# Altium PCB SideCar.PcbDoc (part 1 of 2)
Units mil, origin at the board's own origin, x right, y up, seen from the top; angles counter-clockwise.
Board outline 4800 x 2800 mil, 4 copper layers (Top Layer, GND Plane, Power Routing, Bottom Layer), stack 61.4 mil thick; 116 components, 136 nets, 590 pads, 115 vias.
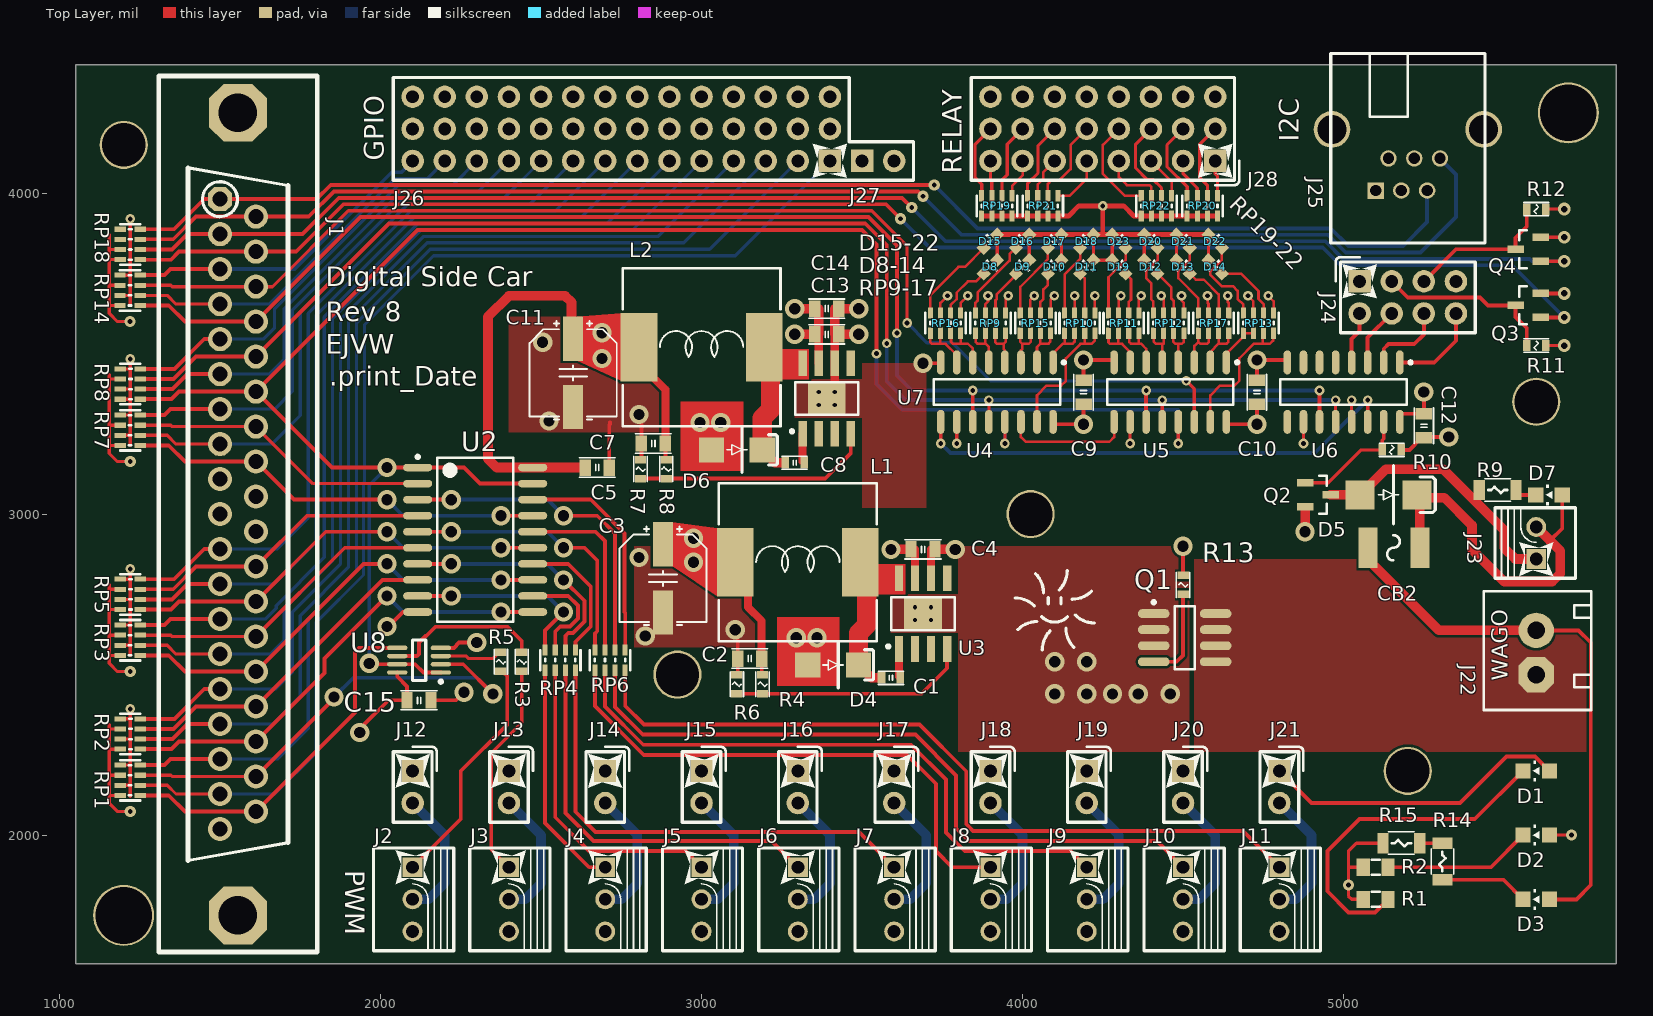
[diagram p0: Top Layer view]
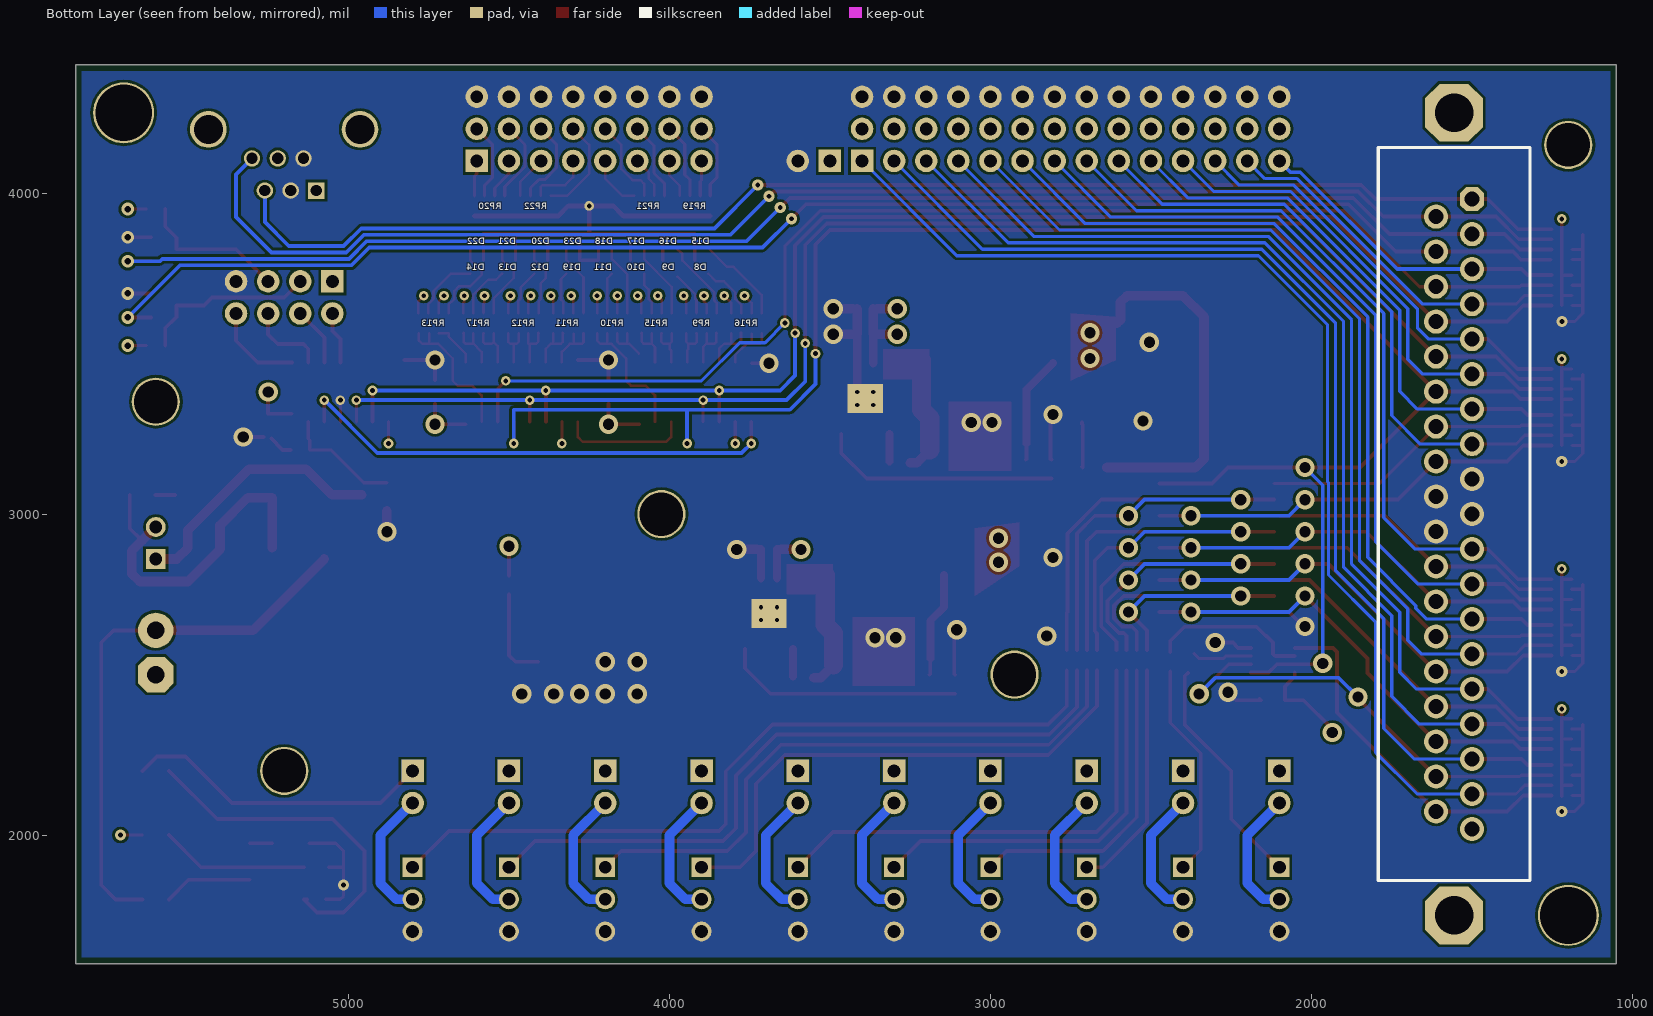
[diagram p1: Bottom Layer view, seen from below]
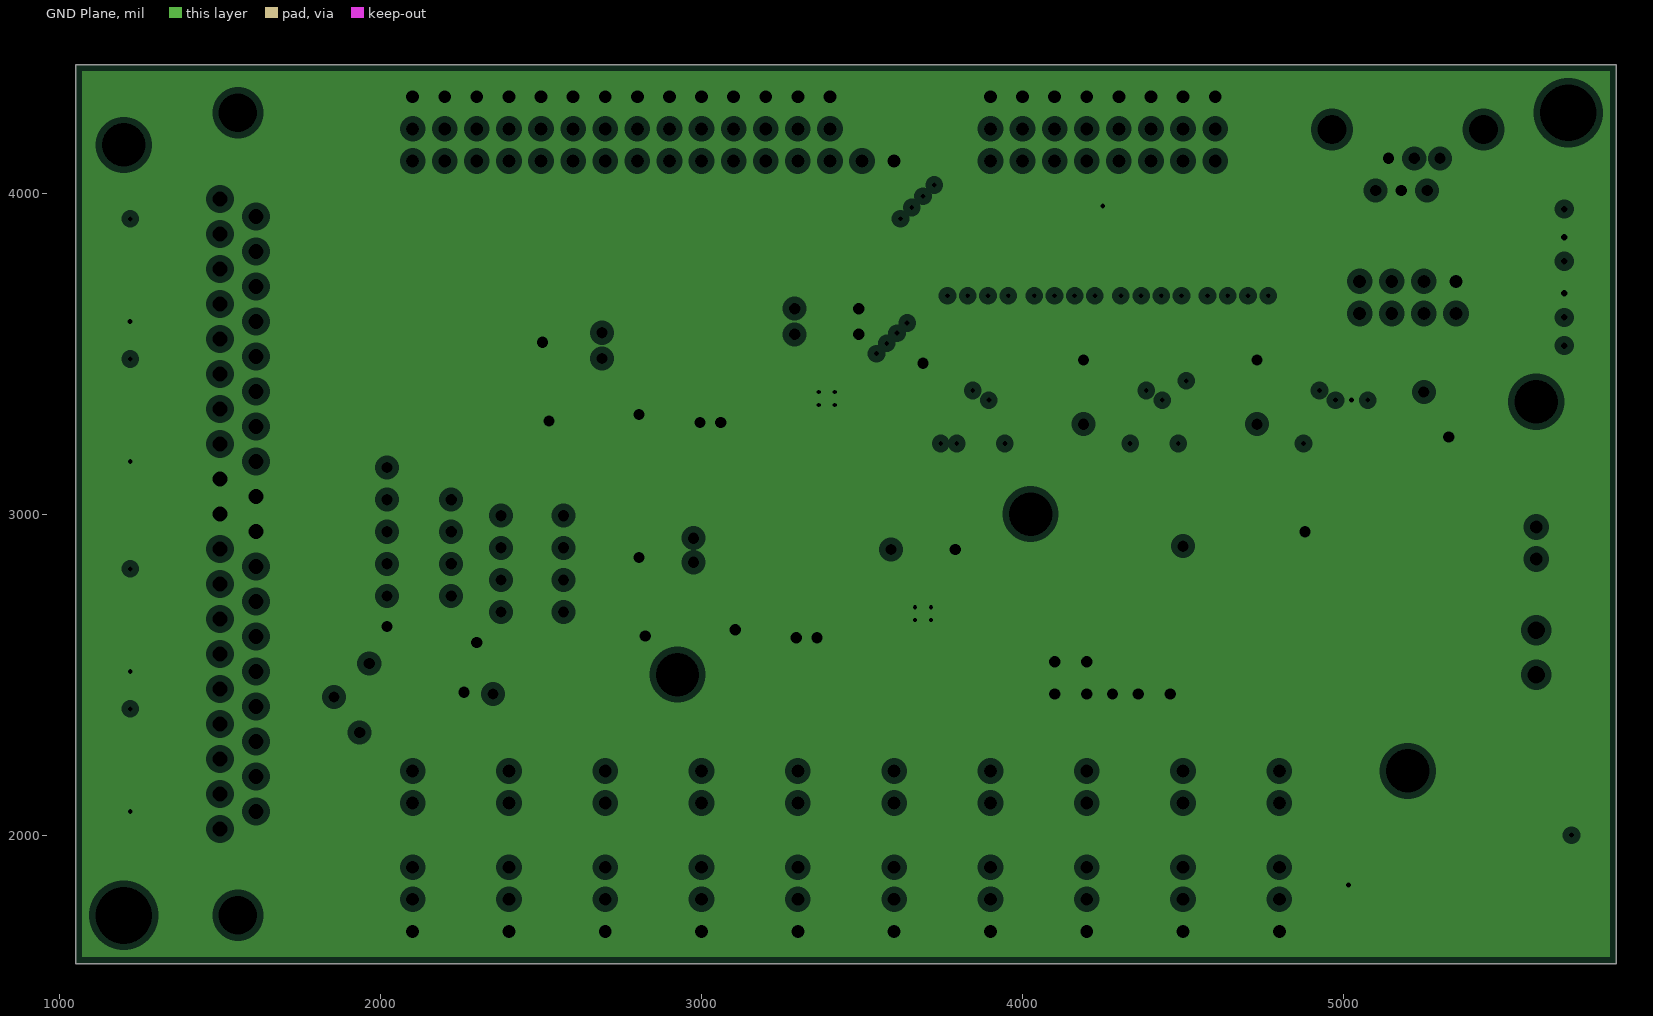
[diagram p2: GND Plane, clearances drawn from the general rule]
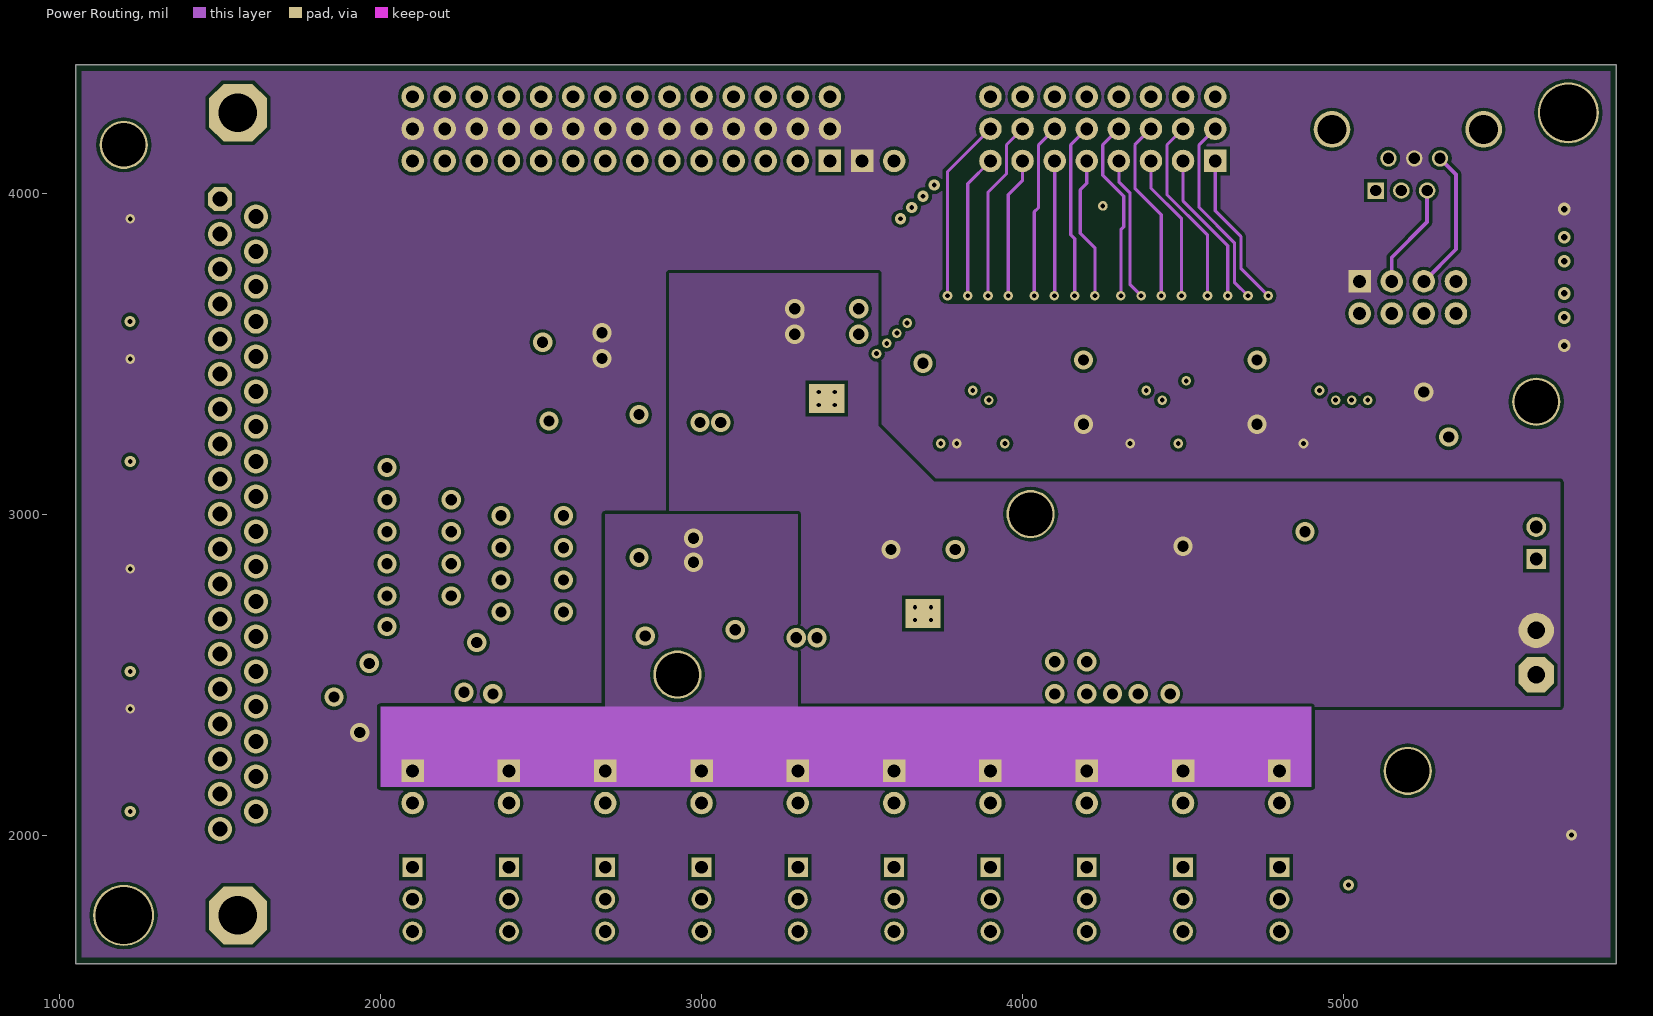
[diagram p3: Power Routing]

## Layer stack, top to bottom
Top Layer: signal copper 1.7
Dielectric: prepreg 12.6, FR-4, Dk 4.8
GND Plane: plane copper 1.4, net GND
Dielectric: core 30, FR-4, Dk 4.8
Power Routing: signal copper 1.4
Dielectric: prepreg 12.6, FR-4, Dk 4.8
Bottom Layer: signal copper 1.7

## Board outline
1050,1600 1050,4400 5850,4400 5850,1600

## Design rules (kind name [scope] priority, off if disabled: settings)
Clearance Clearance_1 [OnLayer('Power Routing')] p1: gap=10
Clearance [All] p2: gap=8
ComponentClearance ComponentClearance_1 [Name = 'J30' vs Name = 'J31'] p1 off: gap=-100 collisioncheckmode=3 verticalgap=-100 showdistances=FALSE
ComponentClearance [All] p2 off: gap=10 collisioncheckmode=3 verticalgap=10 showdistances=FALSE
HoleSize [All] p1: absolutevalues=TRUE maxlimit=250 minlimit=1 maxpercent=80.000 minpercent=20.000
PlaneClearance [All] p1: clearance=20
PlaneConnect [All] p1: planeconnectstyle=Direct reliefexpansion=20 reliefentries=4 reliefconductorwidth=10 reliefairgap=10
PolygonConnect PolygonConnect_2 [All] p1: connectstyle=Direct reliefconductorwidth=10 reliefentries=4 polygonreliefangle="90 Angle"
PolygonConnect PolygonConnect_1 [InNet('BATT_GND')] p2: connectstyle=Direct reliefconductorwidth=10 reliefentries=4 polygonreliefangle="90 Angle"
PolygonConnect [OnLayer('Power Routing')] p3: connectstyle=Direct reliefconductorwidth=10 reliefentries=4 polygonreliefangle="90 Angle"
RoomDefinition "PWM Outputs" [InComponentClass('PWM Outputs')] p1: confinementstyle=ConfineIn formatcopy=TRUE lockcomponents=FALSE outline 1900,1600 5000,1600 5000,2400 2800,2400 2800,3200 1900,3200
RoomDefinition "Relay Outputs" [InComponentClass('Relay Outputs')] p2: confinementstyle=ConfineIn formatcopy=TRUE lockcomponents=FALSE outline 3500,3200 5500,3200 5500,4400 3500,4400
RoutingVias [All] p1: holewidth=35 width=60 viastyle="Through Hole" minholewidth=15 minwidth=30 maxholewidth=250 maxwidth=250
SolderMaskExpansion [All] p1: expansion=4
TestPointUsage [All] p1: valid=0 allowmultiple=FALSE
Testpoint [All] p1: side=15 testpointundercomponent=TRUE minsize=40 maxsize=100 preferedsize=60 minholesize=0 maxholesize=40 preferedholesize=32 testpointgrid=1 style=1023 order=0-112345678
Width [All] p1: maxlimit=300 minlimit=8 preferedwidth=8
15 further rules are at their usual default settings.

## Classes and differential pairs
component class "cRIO Connectors": J1 J25 J26 J27 Q3 Q4 R11 R12 RP1 RP2 RP3 RP5 RP7 RP8 RP14 RP18
component class Power: C1 C2 C3 C4 C7 C8 C11 C13 C14 CB2 D1 D2 D3 D4 D5 D6 D7 J22 J23 L1 L2 Q1 Q2 R1 R2 R4 R6 R7 R8 R9 R10 R13 R14 R15 U3 U7
component class "PWM Outputs": C5 C15 J2 J3 J4 J5 J6 J7 J8 J9 J10 J11 J12 J13 J14 J15 J16 J17 J18 J19 J20 J21 R3 R5 RP4 RP6 U2 U8
component class "Relay Outputs": C9 C10 C12 D8 D9 D10 D11 D12 D13 D14 D15 D16 D17 D18 D19 D20 D21 D22 D23 J24 J28 RP9 RP10 RP11 RP12 RP13 RP15 RP16 RP17 RP19 RP20 RP21 RP22 U4 U5 U6

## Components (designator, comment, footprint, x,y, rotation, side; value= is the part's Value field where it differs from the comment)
C1 "0.01uF 0603" C0603_C 3590,2490 r180 top (schematic designator C7)
C2 "0.1uF 0805 Bypass" C0805_C 3150,2550 r0 top (schematic designator C8)
C3 "330µF SMT - Chemi-Con" "SMT-CAN Nippon F80" 2880,2800 r0 top (schematic designator C9)
C4 "4.7UF 0805 25V X5R" C0805_C 3690,2890 r180 top (schematic designator C5)
C5 "0.1uF 0805 Bypass" C0805_C 2675,3145 r180 top (schematic designator C1)
C7 "0.1uF 0805 Bypass" C0805_C 2850,3220 r0 top (schematic designator C13)
C8 "0.01uF 0603" C0603_C 3290,3160 r180 top (schematic designator C12)
C9 "0.1uF 0805 Bypass" C0805_C 4190,3380 r90 top (schematic designator C3)
C10 "0.1uF 0805 Bypass" C0805_C 4730,3380 r90 top (schematic designator C2)
C11 "330µF SMT - Chemi-Con" "SMT-CAN Nippon F80" 2600,3440 r0 top (schematic designator C14)
C12 "0.1uF 0805 Bypass" C0805_C 5250,3275 r270 top (schematic designator C4)
C13 "4.7UF 0805 25V X5R" C0805_C 3390,3560 r180 top (schematic designator C11)
C14 "4.7UF 0805 25V X5R" C0805_C 3390,3640 r180 top (schematic designator C10)
C15 "0.1uF 0805 Bypass" C0805_C 2120,2420 r180 top
CB2 "1.1 A Hold, 2.2 A Trip" PTC1812 5155,2895 r180 top (schematic designator CB1)
D1 "LTST-C170KGKT" "LED_0805 1.1 Green" 5600,2200 r180 top (schematic designator D27)
D2 "LTST-C170KGKT" "LED_0805 1.1 Green" 5600,2000 r180 top (schematic designator D30)
D3 "LTST-C170KGKT" "LED_0805 1.1 Green" 5600,1800 r180 top (schematic designator D25)
D4 "MBRA340T3G" SMA 3410,2530 r0 top (schematic designator D29)
D5 "25ns 2A Standard Rectifier" SMB 5140,3060 r0 top (schematic designator D17)
D6 "MBRA340T3G" SMA 3110,3200 r0 top (schematic designator D32)
D7 "LTST-C170KGKT" "LED_0805 1.1 Green" 5640,3060 r180 top (schematic designator D15)
D8 "LNJ308G8LRA" "LED_0603 0.8 GREEN" 3900,3770 r45 top (schematic designator D16)
D9 "LNJ308G8LRA" "LED_0603 0.8 GREEN" 4000,3770 r45 top (schematic designator D13)
D10 "LNJ308G8LRA" "LED_0603 0.8 GREEN" 4100,3770 r45 top (schematic designator D11)
D11 "LNJ308G8LRA" "LED_0603 0.8 GREEN" 4200,3770 r45 top (schematic designator D9)
D12 "LNJ308G8LRA" "LED_0603 0.8 GREEN" 4400,3770 r135 top (schematic designator D5)
D13 "LNJ308G8LRA" "LED_0603 0.8 GREEN" 4500,3770 r135 top (schematic designator D3)
D14 "LNJ308G8LRA" "LED_0603 0.8 GREEN" 4600,3770 r135 top (schematic designator D1)
D15 "LNJ808R8ERA" "LED_0603 0.8ORANGE" 3900,3850 r45 top (schematic designator D18)
D16 "LNJ808R8ERA" "LED_0603 0.8ORANGE" 4000,3850 r45 top (schematic designator D14)
D17 "LNJ808R8ERA" "LED_0603 0.8ORANGE" 4100,3850 r45 top (schematic designator D12)
D18 "LNJ808R8ERA" "LED_0603 0.8ORANGE" 4200,3850 r45 top (schematic designator D10)
D19 "LNJ308G8LRA" "LED_0603 0.8 GREEN" 4300,3770 r135 top (schematic designator D7)
D20 "LNJ808R8ERA" "LED_0603 0.8ORANGE" 4400,3850 r135 top (schematic designator D6)
D21 "LNJ808R8ERA" "LED_0603 0.8ORANGE" 4500,3850 r135 top (schematic designator D4)
D22 "LNJ808R8ERA" "LED_0603 0.8ORANGE" 4600,3850 r135 top (schematic designator D2)
D23 "LNJ808R8ERA" "LED_0603 0.8ORANGE" 4300,3850 r135 top (schematic designator D8)
J1 "DB37" "DB37- THRU" 1556,3000 r90 top (schematic designator J24)
J2 "KK Friction Lock" KK100P3 2100,1900 r270 top (schematic designator J19)
J3 "KK Friction Lock" KK100P3 2400,1900 r270 top (schematic designator J17)
J4 "KK Friction Lock" KK100P3 2700,1900 r270 top (schematic designator J15)
J5 "KK Friction Lock" KK100P3 3000,1900 r270 top (schematic designator J13)
J6 "KK Friction Lock" KK100P3 3300,1900 r270 top (schematic designator J11)
J7 "KK Friction Lock" KK100P3 3600,1900 r270 top (schematic designator J9)
J8 "KK Friction Lock" KK100P3 3900,1900 r270 top (schematic designator J7)
J9 "KK Friction Lock" KK100P3 4200,1900 r270 top (schematic designator J5)
J10 "KK Friction Lock" KK100P3 4500,1900 r270 top (schematic designator J3)
J11 "KK Friction Lock" KK100P3 4800,1900 r270 top (schematic designator J1)
J12 "Jumper" H100P2 2100,2200 r270 top (schematic designator J20)
J13 "Jumper" H100P2 2400,2200 r270 top (schematic designator J18)
J14 "Jumper" H100P2 2700,2200 r270 top (schematic designator J16)
J15 "Jumper" H100P2 3000,2200 r270 top (schematic designator J14)
J16 "Jumper" H100P2 3300,2200 r270 top (schematic designator J12)
J17 "Jumper" H100P2 3600,2200 r270 top (schematic designator J10)
J18 "Jumper" H100P2 3900,2200 r270 top (schematic designator J8)
J19 "Jumper" H100P2 4200,2200 r270 top (schematic designator J6)
J20 "Jumper" H100P2 4500,2200 r270 top (schematic designator J4)
J21 "Jumper" H100P2 4800,2200 r270 top (schematic designator J2)
J22 "3.5mm Mini Header" "WAGO 734-132" 5600,2500 r90 top (schematic designator J28)
J23 "KK Friction Lock" KK100P2 5600,2860 r90 top (schematic designator J22)
J24 "THRU VERT" "H100P2x4 TSW-104-07-T-D" 5050,3725 r0 top (schematic designator J23)
J25 "NXT Port" "NXT RJ" 5200,4198.43 r0 top (schematic designator J27)
J26 "3x12 Bird Pins" "H100P3x14 TSW-114-07-T-T" 3400,4100 r180 top locked (schematic designator J25)
J27 "THRU VERT" H100P2 3500,4100 r0 top (schematic designator J26)
J28 "3x8 Bird Pins" "H100P3x8 TSW-108-07-T-T" 4600,4100 r180 top (schematic designator J21)
L1 "22 µH 3.37 A" "Wurth WE-PD L" 3300,2850 r270 top
L2 "22 µH 3.37 A" "Wurth WE-PD L" 3000,3520 r270 top
Q1 "FDS8817NZ" "SO-8_M FET" 4505,2615 r0 top (schematic designator Q3)
Q2 "FDN359AN" "SOT-23 FET" 4920,3060 r0 top (schematic designator Q1)
Q3 "FDV301N" "SOT-23 FET" 5575,3650 r180 top (schematic designator Q2)
Q4 "FDV301N" "SOT-23 FET" 5575,3825 r180 top
R1 "200 ohm 0805 1%" R0805_M 5100,1800 r0 top (schematic designator R12)
R2 "150 ohm 0805 1%" R0805_M 5100,1900 r0 top (schematic designator R15)
R3 "470 ohm 0603 1%" R0603_C 2440,2540 r90 top (schematic designator R1)
R4 "2.55k ohm 0603 1%" R0603_C 3190,2470 r90 top (schematic designator R10)
R5 "470 ohm 0603 1%" R0603_C 2375,2540 r90 top (schematic designator R2)
R6 "10k ohm 0603 1%" R0603_C 3110,2470 r270 top (schematic designator R11)
R7 "10k ohm 0603 1%" R0603_C 2810,3140 r270 top (schematic designator R14)
R8 "30.9k ohm 0603 1%" R0603_C 2890,3140 r90 top (schematic designator R13)
R9 "680 ohm 1206 5%" R1206_C 5480,3075 r0 top (schematic designator R3)
R10 "10k ohm 0603 1%" R0603_C 5150,3200 r180 top (schematic designator R4)
R11 "3.16k ohm 0603 1%" R0603_C 5600,3525 r0 top (schematic designator R5)
R12 "3.16k ohm 0603 1%" R0603_C 5600,3950 r0 top (schematic designator R7)
R13 "10k ohm 0603 1%" R0603_C 4500,2779.53 r90 top (schematic designator R6)
R14 "270 ohm 1206 5%" R1206_C 5307.91,1917.91 r270 top (schematic designator R8)
R15 "240 ohm 1206 5%" R1206_C 5180,1975 r0 top (schematic designator R9)
RP1 "4x0603 10K" "R0603x4 - Convex" 1220.22,2170.79 r180 top (schematic designator RP18)
RP2 "4x0603 10K" "R0603x4 - Convex" 1220.68,2315 r180 top (schematic designator RP22)
RP3 "4x0603 10K" "R0603x4 - Convex" 1220.22,2607.02 r180 top (schematic designator RP17)
RP4 "4x0603 330" "R0603x4 - Convex" 2560,2545 r90 top (schematic designator RP1)
RP5 "4x0603 10K" "R0603x4 - Convex" 1220.68,2750 r180 top (schematic designator RP21)
RP6 "4x0603 330" "R0603x4 - Convex" 2715,2545 r90 top (schematic designator RP2)
RP7 "4x0603 10K" "R0603x4 - Convex" 1220.22,3261.02 r180 top (schematic designator RP16)
RP8 "4x0603 10K" "R0603x4 - Convex" 1220.68,3405 r180 top (schematic designator RP20)
RP9 "4x0603 680" "R0603x4 - Convex" 3900,3595 r270 top (schematic designator RP13)
RP10 "4x0603 680" "R0603x4 - Convex" 4177.99,3595 r270 top (schematic designator RP11)
RP11 "4x0603 680" "R0603x4 - Convex" 4315,3595 r270 top (schematic designator RP10)
RP12 "4x0603 680" "R0603x4 - Convex" 4455,3595 r270 top (schematic designator RP8)
RP13 "4x0603 680" "R0603x4 - Convex" 4735,3595 r270 top (schematic designator RP4)
RP14 "4x0603 10K" "R0603x4 - Convex" 1220,3697.01 r180 top (schematic designator RP15)
RP15 "4x0603 680" "R0603x4 - Convex" 4040,3595 r270 top (schematic designator RP12)
RP16 "4x0603 680" "R0603x4 - Convex" 3760,3595 r270 top (schematic designator RP14)
RP17 "4x0603 680" "R0603x4 - Convex" 4595,3595 r270 top (schematic designator RP6)
RP18 "4x0603 10K" "R0603x4 - Convex" 1220.46,3840 r180 top (schematic designator RP19)
RP19 "4x0603 10K" "R0603x4 - Convex" 3920,3960 r270 top (schematic designator RP9)
RP20 "4x0603 10K" "R0603x4 - Convex" 4560,3960 r270 top (schematic designator RP3)
RP21 "4x0603 10K" "R0603x4 - Convex" 4062.99,3960 r270 top (schematic designator RP7)
RP22 "4x0603 10K" "R0603x4 - Convex" 4417.01,3960 r270 top (schematic designator RP5)
U2 "SN74AC244DWR" DW020_N 2295,2920 r0 top
U3 "Buck Converter" TPS543X 3690,2690 r90 top (schematic designator U5)
U4 "SN74LV595ADR Shift Register" D016_L 3920,3380 r270 top (schematic designator U3)
U5 "SN74LV595ADR Shift Register" D016_L 4460,3380 r270 top (schematic designator U2)
U6 "SN74LV595ADR Shift Register" D016_L 5000,3380 r270 top (schematic designator U4)
U7 "Buck Converter" TPS543X 3390,3360 r90 top (schematic designator U6)
U8 "Dual Buffer" TSOP65P400X130-8N 2120,2545 r180 top

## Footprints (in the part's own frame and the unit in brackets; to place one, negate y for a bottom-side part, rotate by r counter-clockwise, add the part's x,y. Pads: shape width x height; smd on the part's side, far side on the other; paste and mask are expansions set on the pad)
C0603_C [mm]
  rect 0.6x0.9 smd: 1(-0.75,0) 2(0.75,0)
  silkscreen extent -1,-0.53 1,0.53, body extent -0.85,-0.45 0.85,0.45, height 0.9
C0805_C [mm]
  rect 0.9x1.3 smd: 1(-0.95,0) 2(0.95,0)
  silkscreen extent -1.42,-0.76 1.42,0.76, body extent -1.02,-0.64 1.02,0.64, height 1.25
D016_L [mm] "16-Pin Small Outline Integrated Circuit 1.27 mm Pitch, IPC High Density"
  oval 1.9x0.6 smd: 1(-2.35,4.445) 2(-2.35,3.175) 3(-2.35,1.905) 4(-2.35,0.635) 5(-2.35,-0.635) 6(-2.35,-1.905) 7(-2.35,-3.175) 8(-2.35,-4.445) 9(2.35,-4.445) 10(2.35,-3.175) 11(2.35,-1.905) 12(2.35,-0.635) 13(2.35,0.635) 14(2.35,1.905) 15(2.35,3.175) 16(2.35,4.445)
  silkscreen extent -2.47,-5 1,5.42, body extent -1.95,-4.95 1.95,4.95, height 1.75
"DB37- THRU" [mil]
  oct 75x75 hole 47: 1(980.98,55.98)
  round 75 hole 47: 2(872,56) 3(763,56) 4(654,56) 5(545,56) 6(436,56) 7(327,56) 8(218,56) 9(109,56) 10(0,56) 11(-109,56) 12(-218,56) 13(-327,56) 14(-436,56) 15(-545,56) 16(-654,56) 17(-763,56) 18(-872,56) 19(-980.98,55.98) 20(926.5,-56) 21(817.5,-56) 22(708.5,-56) 23(599.5,-56) 24(490.5,-56) 25(381.5,-56) 26(272.5,-56) 27(163.5,-56) 28(54.5,-56) 29(-54.5,-56) 30(-163.5,-56) 31(-272.5,-56) 32(-381.5,-56) 33(-490.5,-56) 34(-599.5,-56) 35(-708.5,-56) 36(-817.5,-56) 37(-926.5,-56)
  oct 180x180 hole 120: ""(-1250,0) ""(1250,0)
  silkscreen extent -1364,-247 1365,247, body extent -1372,-255 1372,255, height 696
DW020_N [mm] "20-Pin Plastic Small Outline Integrated Circuit 1.27 mm Pitch, IPC Medium Density"
  oval 2.3x0.6 smd: 1(-4.55,5.715) 2(-4.55,4.445) 3(-4.55,3.175) 4(-4.55,1.905) 5(-4.55,0.635) 6(-4.55,-0.635) 7(-4.55,-1.905) 8(-4.55,-3.175) 9(-4.55,-4.445) 10(-4.55,-5.715) 11(4.55,-5.715) 12(4.55,-4.445) 13(4.55,-3.175) 14(4.55,-1.905) 15(4.55,-0.635) 16(4.55,0.635) 17(4.55,1.905) 18(4.55,3.175) 19(4.55,4.445) 20(4.55,5.715)
  silkscreen extent -4.67,-6.5 3,6.69, body extent -3.75,-6.4 3.75,6.4, height 2.65
H100P2 [mil] "Header 100mil, 2POS THRU VERT"
  rect 70x70 hole 40: 1(0,0)
  round 70 hole 40: 2(100,0)
  silkscreen extent -75,-60 160,75, body extent -60,-60 160,60, height 430
"H100P2x4 TSW-104-07-T-D" [mil] "Header 100mil, 2x4POS THRU VERT"
  rect 70x70 hole 40: 1(0,0)
  round 70 hole 40: 2(0,-100) 3(100,0) 4(100,-100) 5(200,0) 6(200,-100) 7(300,0) 8(300,-100)
  silkscreen extent -75,-160 360,75, body extent -60,-160 360,60, height 430
"H100P3x8 TSW-108-07-T-T" [mil] "Header 100mil, 3x8POS THRU VERT"
  rect 70x70 hole 40: 1(0,0)
  round 70 hole 40: 2(0,-100) 3(0,-200) 4(100,0) 5(100,-100) 6(100,-200) 7(200,0) 8(200,-100) 9(200,-200) 10(300,0) 11(300,-100) 12(300,-200) 13(400,0) 14(400,-100) 15(400,-200) 16(500,0) 17(500,-100) 18(500,-200) 19(600,0) 20(600,-100) 21(600,-200) 22(700,0) 23(700,-100) 24(700,-200)
  silkscreen extent -75,-260 760,75, body extent -60,-260 760,60, height 430
"H100P3x14 TSW-114-07-T-T" [mil] "Header 100mil, 3x14POS THRU VERT"
  rect 70x70 hole 40: 1(0,0)
  round 70 hole 40: 2(0,-100) 3(0,-200) 4(100,0) 5(100,-100) 6(100,-200) 7(200,0) 8(200,-100) 9(200,-200) 10(300,0) 11(300,-100) 12(300,-200) 13(400,0) 14(400,-100) 15(400,-200) 16(500,0) 17(500,-100) 18(500,-200) 19(600,0) 20(600,-100) 21(600,-200) 22(700,0) 23(700,-100) 24(700,-200) 25(800,0) 26(800,-100) 27(800,-200) 28(900,0) 29(900,-100) 30(900,-200) 31(1000,0) 32(1000,-100) 33(1000,-200) 34(1100,0) 35(1100,-100) 36(1100,-200) 37(1200,0) 38(1200,-100) 39(1200,-200) 40(1300,0) 41(1300,-100) 42(1300,-200)
  silkscreen extent -60,-260 1360,60, body extent -60,-260 1360,60, height 430
KK100P2 [mm] "KK Friction Lock Header 100mil, 2POS"
  rect 1.575x1.575 hole 1.02: 1(0,0)
  round 1.575 hole 1.02: 2(2.54,0)
  silkscreen extent -1.52,-3.1 4.06,3.25, body extent -1.52,-3.1 4.06,3.25, height 8.18
KK100P3 [mm] "KK Friction Lock Header 100mil, 3POS"
  rect 1.575x1.575 hole 1.016: 1(0,0)
  round 1.575 hole 1.016: 2(2.54,0) 3(5.08,0)
  silkscreen extent -1.52,-3.1 6.6,3.25, body extent -1.52,-3.1 6.6,3.25, height 8.18
"LED_0603 0.8 GREEN" [mm] "0.8mm Green 0603 Led"
  rect 0.8x0.8 smd: A(-0.75,0) K(0.75,0)
  silkscreen extent -0.2,-0.62 0.25,0.62, body extent -0.8,-0.4 0.8,0.4, height 0.8
"LED_0603 0.8ORANGE" [mm] "0.8mm Orange 0603 Led"
  rect 0.8x0.8 smd: A(-0.75,0) K(0.75,0)
  silkscreen extent -0.2,-0.62 0.25,0.62, body extent -0.8,-0.4 0.8,0.4, height 0.8
"LED_0805 1.1 Green" [mm] "1.1mm Green 0805 Led"
  rect 1.2x1.2 smd: A(-1.05,0) K(1.05,0)
  silkscreen extent -0.25,-0.82 0.28,0.82, body extent -1,-0.63 1,0.63, height 1.1
"NXT RJ" [mm] "NXT Compatible RJ-12 Jack"
  rect 1.3x1.3 hole 0.9: 1(-2.55,-4.84)
  round 1.3 hole 0.9: 2(-1.53,-2.3) 3(-0.51,-4.84) 4(0.51,-2.3) 5(1.53,-4.84) 6(2.55,-2.3)
  round 2.9 hole 2.3: MH(-6,0) MH(6,0)
  silkscreen extent -6.1,-9 6.1,6, body extent -7.27,-9 7.27,6, height 14.53
PTC1812 [mm]
  rect 1.5x3.2 smd: 1(-2.1,0) 2(2,0)
  silkscreen extent -0.5,-1 0.5,1, body extent -2.4,-1.7 2.4,1.7, height 2
R0603_C [mm]
  rect 0.6x0.9 smd: 1(-0.75,0) 2(0.75,0)
  silkscreen extent -1,-0.53 1,0.53, body extent -0.75,-0.4 0.75,0.4, height 0.4
"R0603x4 - Convex" [mm]
  rect 0.9x0.4 smd: 1(-0.8,1.2) 2(0.8,1.2) 3(-0.8,0.4) 4(0.8,0.4) 5(-0.8,-0.4) 6(0.8,-0.4) 7(-0.8,-1.2) 8(0.8,-1.2)
  silkscreen extent -0.8,-1.6 0.8,1.6, body extent -0.8,-1.6 0.8,1.6, height 0.5
R0805_M [mm] "Chip Resistor, 2-Leads, Body 2.0x1.3mm, IPC Medium Density"
  rect 1.05x1.35 smd: 1(-0.975,0) 2(0.975,0)
  silkscreen extent -0.33,-0.58 0.33,0.58, body extent -1.05,-0.67 1.05,0.67, height 0.6
R1206_C [mm]
  rect 0.9x1.6 smd: 1(-1.45,0) 2(1.45,0)
  silkscreen extent -1.02,-0.89 1.02,0.89, body extent -1.5,-0.9 1.5,0.9, height 0.4
SMA [mm] "DO-214-AC/SMA; 2 C-Bend Leads; Body 5.6 x 2.9 mm, inc. leads (LxW)"
  rect 2x2 smd: A(-2,0) K(2,0)
  silkscreen extent -0.8,-1.8 3.2,1.8, body extent -2.3,-1.5 2.3,1.5, height 2.4
SMB [mm] "DO-214-AA/SMB; 2 C-Bend Leads; Body 5.3 x 3.6 mm, inc. leads (LxW)"
  rect 2.3x2.3 smd: A(-2.25,0) K(2.25,0)
  silkscreen extent -0.8,-2.3 3.7,2.3, body extent -2.36,-1.96 2.36,1.96, height 2.4
"SMT-CAN Nippon F80" [mm] "Nippon ChemiCon SMT-CAN type Capacitor, Size code F80"
  rect 1.6x3.5 smd: +(0,2.7) -(0,-2.7)
  silkscreen extent -3.45,-3.7 3.45,4.1, body extent -3.3,-3.3 3.3,3.3, height 7.7
"SO-8_M FET" [mm] "8-Pin Plastic Small Outline Integrated Circuit 1.27 mm Pitch, IPC Low Density"
  oval 2.5x0.7 smd: D(2.45,-1.905) D(2.45,-0.635) D(2.45,0.635) D(2.45,1.905) G(-2.45,-1.905) S(-2.45,-0.635) S(-2.45,0.635) S(-2.45,1.905)
  silkscreen extent -2.57,-2.5 0.8,2.93, body extent -2,-2.5 2,2.5, height 1.75
"SOT-23 FET" [mm]
  rect 1.3x0.6 smd: D(1,0) G(-1,0.95) S(-1,-0.95)
  silkscreen extent 0.1,-1.5 0.7,1.5, body extent -0.7,-1.5 0.7,1.5, height 0.97
TPS543X [mil] "Thermally Enhanced SO8"
  rect 80x25.98 smd: 1(-110,75) 2(-110,25) 3(-110,-25) 4(-110,-75)
  rect 80x26 smd: 5(110,-75) 6(110,-25) 7(110,25) 8(110,75)
  rect 50x60 hole 12.99: PAD(-20,-25) PAD(-20,25) PAD(20,-25) PAD(20,25)
  rect 97.99x117.99 smd: PAD(0,0)
  silkscreen extent -107,-98 51,113, body extent -79,-98 79,98, height 69
TSOP65P400X130-8N [mm] "TSOP, 8-Leads, Body 3.2x2.9mm (max), Pitch 0.65mm, IPC Medium Density"
  oval 1.6x0.35 smd: 1(-1.725,0.975) 2(-1.725,0.325) 3(-1.725,-0.325) 4(-1.725,-0.975) 5(1.725,-0.975) 6(1.725,-0.325) 7(1.725,0.325) 8(1.725,0.975)
  silkscreen extent -1.85,-1.6 0.53,1.82, body extent -1.45,-1.58 1.45,1.57, height 1.3
"WAGO 734-132" [mm] "3.5mm 10 A Protected Header"
  oct 2.8x2.8 hole 1.4: 1(0,0)
  round 2.8 hole 1.4: 2(3.5,0)
  silkscreen extent -2.8,-4.35 6.6,4.15, body extent -3.25,-4.35 6.6,9.1, height 22.4
"Wurth WE-PD L" [mm] "SMT Power Inductors"
  rect 5.4x2.9 smd: 1(0,4.95) 2(0,-4.95)
  silkscreen extent -6.25,-6.25 6.25,6.25, body extent -6,-6 6,6, height 6

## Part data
C1 C8: library part "0.01 uF 0603 50V"
C2 C5 C7 C9 C10 C12 C15: "Capacitor"
C3 C11: library part "330µF 6.3V CAN-SMT", "330µF 6.3V ELECT CAN-SMT"
C4 C13 C14: library part "4.7uF 0805 25V X5R", "CERAMIC 4.7uF 25V X5R 0805"
CB2: library part MF-MSMF110/16-2, "PTC 1.1A /  2.2A SMT"
D1 D2 D3 D7: "Green 0805 20mA 2.0V 35mCd"
D4 D6: "3A Schottky Diode"
D5: library part ES2A-13-F
D8 D9 D10 D11 D12 D13 D14 D19: "Green 0603 5mA 1.9V 3mCd"
D15 D16 D17 D18 D20 D21 D22 D23: "Orange 0603 5mA 1.8V 1.1mCd"
J1: library part "DB37 Female THRU", "D-SUB RCPT STR 37POS PCB AU"
J2 J3 J4 J5 J6 J7 J8 J9 J10 J11: library part KK100P3
J12 J13 J14 J15 J16 J17 J18 J19 J20 J21: library part "Jumper 100mil"
J22: library part "WAGO 734-132", "3.5mm Header Protected against Mismating"
J23: library part KK100P2
J24: library part "H100 2x4 THRU VERT", "2x4 Bird Pins"
J25: library part "NXT RJ12 Connector", "NXT RJ12 Connector"
J26: library part "H100 3x14 THRU VERT", "3x14 Bird Pins"
J27: library part "H100 1x2 THRU VERT", "1x2 Bird Pins"
J28: library part "H100 3x8 THRU VERT"
L1 L2: library part "WE-PD-L 22", "22 µH 3.37 A 20% SMD"
Q1: "N-CH 30V 8SOIC, ESD Protected"
Q2: "N-Channel Powertrench MOSFET, 30V, 2.7A, 2.5mOhm"
Q3 Q4: "N-Ch Logic FET, 25V, 0.22A, 5 Ohm"
R3 R5: library part "330 ohm 0603 1%", "330 ohm 0603 1%"
R4: library part "39.2k ohm 0603 1%", "39.2k ohm 0603 1%"
RP1 RP3 RP7 RP14 RP20 RP21: library part "10k 5% 4x0603 Isolated", "10K 5% Isolated Resistor Network"
RP2 RP5 RP8 RP18 RP19 RP22: library part "10K 5% 4x0603 Isolated", "10K 5% Isolated Resistor Network"
RP4 RP6: library part "330 5% 4x0603 Isolated", "330 5% Isolated Resistor Network"
RP9 RP10 RP11 RP12 RP13 RP15 RP16 RP17: library part "680 5% 4x0603 Isolated", "680 5% Isolated Resistor Network"
U2: "8x Line Driver, Non-Inverting"
U3 U7: library part TPS5431, "3-A, WIDE INPUT RANGE, STEP-DOWN SWIFT CONVERTER"
U4 U5 U6: "8 bit Shift Register with D Latching"
U8: library part "SN74LVC2G125DCTR Dual Buffer"

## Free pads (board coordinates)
  round 30 hole 15: 0(4250,3960)
  round 190 hole 177: MH(1200,1750) MH(5700,4250)
  round 150 hole 135: MH(1200,4150) MH(2925,2500) MH(4025,3000) MH(5200,2200) MH(5600,3350)

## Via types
v1: diameter 60, hole 35, Top Layer to Bottom Layer, 60 vias
v2: diameter 30, hole 15, Top Layer to Bottom Layer, 39 vias
v3: diameter 35, hole 15, Top Layer to Bottom Layer, 10 vias
v4: diameter 40, hole 20, Top Layer to Bottom Layer, 6 vias

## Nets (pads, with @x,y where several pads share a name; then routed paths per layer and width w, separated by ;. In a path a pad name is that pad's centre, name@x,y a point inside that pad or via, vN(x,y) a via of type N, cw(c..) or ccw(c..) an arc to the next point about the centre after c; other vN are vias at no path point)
5V: C5.2 C7.2 C9.1 C10.1 C11.+ C12.1 C15.2 D2.A J24.1 J25.4 J26.2 J26.5 J26.8 J26.11 J26.14 J26.17 J26.20 J26.23 J26.26 J26.29 J26.32 J26.35 J26.38 J26.41 J27.1 L2.2 R8.2 R11.2 R12.2 RP1.4 RP1.8 RP2.4 RP2.8 RP3.4 RP3.8 RP5.4 RP5.8 RP7.4 RP7.8 RP8.2 RP8.4 RP8.8 RP14.4 RP14.8 U2.20 U4.10 U4.16 U5.10 U5.16 U6.10 U6.16 U8.8 | length 4714.5
  Top Layer w10: RP14.4@1188.5,3681.26 1220.46,3681.26 ; RP14.8@1188.5,3744.25 1220.46,3744.25 ; RP1.4@1188.72,2155.04 1220.22,2155.04 ; RP1.8@1188.72,2218.03 1220.22,2218.03 ; RP3.4@1188.72,2591.28 1220.22,2591.28 ; RP3.8@1188.72,2654.27 1220.22,2654.27 ; RP7.4@1188.72,3245.28 1220.22,3245.28 ; RP7.8@1188.72,3308.27 1220.22,3308.27 ; RP2.4@1189.18,2299.25 1220.68,2299.25 ; RP2.8@1189.18,2362.24 1220.68,2362.24 ; RP5.4@1189.18,2734.25 1220.68,2734.25 ; RP5.8@1189.18,2797.24 1220.68,2797.24 ; RP8.2@1189.18,3357.76 1220.68,3357.76 ; RP8.4@1189.18,3389.25 1220.68,3389.25 ; RP8.8@1189.18,3452.24 1220.68,3452.24 ; 1220.46,3650.46 1220.46,3681.26 ; v2(1220.46,3919.54) 1220.46,3744.25 ; 1220.68,2120 1220.68,2299.25 ; v2(1220.68,2393.32) 1220.68,2362.24 ; 1220.68,2560.24 1220.68,2797.24 ; v2(1220.68,2829.32) 1220.68,2797.24 ; 1220.68,3214.24 1220.68,3357.76 ; v2(1220.68,3483.32) 1220.68,3452.24 ; v2(3795,3219.96) U4.10@3795,3287.48 ; v2(4335,3219.96) U5.10@4335,3287.48 ; v2(4875,3219.96) U6.10@4875,3287.48 ; R11.2@5629.53,3525 v4(5687.4,3525) ; R12.2@5629.53,3950 v4(5687.4,3950) ; D2.A@5641.34,2000 v3(5710,2000) ; 1220.46,3681.26 1220.46,3744.25 ; 1220.68,2299.25 1220.68,2362.24 ; 1220.68,3357.76 1220.68,3389.25 ; 1220.68,3389.25 1220.68,3452.24
  Top Layer w12: v1(1935,2320) 1935,2330 2025,2420 C15.2@2080,2420 ; U8.8@2052.09,2506.61 2052.09,2493.82 2082.6,2463.31 C15.2@2082.6,2420 ; C7.2@2887.4,3220 2887.4,3172.13 R8.2@2890,3169.53 ; C9.1@4190,3342.6 v1(4190,3280) ; C10.1@4730,3342.6 v1(4730,3280) ; U6.16@5177.6,3312.4 C12.1@5250,3312.4 v1(5250,3380) ; U4.16@4095,3280 v1(4190,3280) ; U4.16@4095,3280 v1(4190,3280) ; U4.16@4095,3280 v1(4190,3280) ; U4.16@4095,3280 v1(4190,3280) ; U5.16@4635,3280 v1(4730,3280) ; U5.16@4635,3280 v1(4730,3280) ; U5.16@4635,3280 v1(4730,3280) ; U5.16@4635,3280 v1(4730,3280)
  Top Layer w25: L2.2@2805,3470 2887.4,3387.6 C7.2@2887.4,3220
  Top Layer w30: C11.+@2605,3595 2595,3605 2595,3660 2575,3680 2400,3680 2335,3615 2335,3171.97 2361.97,3145 U2.20@2474.13,3145 C5.2@2637.6,3145
  other v1: 2690,3485 2690,3565
6V: C2.2 C3.+ D1.A J12.1 J13.1 J14.1 J15.1 J16.1 J17.1 J18.1 J19.1 J20.1 J21.1 L1.2 R4.2 | length 1290.8
  Top Layer w12: C2.2@3187.4,2550 3187.4,2502.13 R4.2@3190,2499.53 ; J21.1@4800,2200 4900,2100 5362.5,2100 5507.81,2245.31 5596.03,2245.31 D1.A@5641.34,2200
  Top Layer w25: L1.2@3144.96,2810 3144.96,2710.04 3187.4,2667.6 C2.2@3187.4,2550
  other v1: 2975,2850 2975,2925
/OUTPUT_EN: J1.25 RP8.1 U2.1 U2.19 U4.13 U5.13 U8.1 U8.7 | length 8820.2
  Top Layer w10: v2(3945,3219.96) U4.13@3945,3287.48 ; v2(4485,3219.96) U5.13@4485,3287.48
  Top Layer w12: U8.1@2187.91,2506.61 2133.39,2506.61 2107.8,2532.2 U8.7@2052.09,2532.2 ; U2.19@2474.13,3095 2310,3095 2260,3145 U2.1@2115.87,3145 v1(2020,3145) 1848.5,3145 J1.25@1612,3381.5 ; v2(3545,3500) 3545,3840 3500,3885 2115,3885 ; RP8.1@1251.72,3357.99 RP8.1@1252.17,3357.99 ; RP8.1@1251.72,3357.99 RP8.1@1252.17,3357.99 ; RP8.1@1251.72,3357.99 RP8.1@1252.17,3357.99 ; RP8.1@1251.72,3357.99 RP8.1@1252.17,3357.99 ; RP8.1@1252.17,3357.99 1348.81,3357.99 ; RP8.1@1252.17,3357.99 1348.81,3357.99 ; RP8.1@1252.17,3357.99 1348.81,3357.99 ; RP8.1@1252.17,3357.99 1348.81,3357.99 ; 1348.81,3357.99 1372.34,3381.52 J1.25@1611.52,3381.52 ; J1.25@1611.52,3381.52 J1.25@1611.75,3381.75 ; J1.25@1611.52,3381.52 J1.25@1611.75,3381.75 ; J1.25@1611.52,3381.52 J1.25@1611.75,3381.75 ; J1.25@1611.52,3381.52 J1.25@1611.75,3381.75 ; J1.25@1611.52,3381.52 J1.25@1612,3381.5 ; J1.25@1611.5,3381.5 J1.25@1612,3381.5 ; J1.25@1611.75,3381.75 2115,3885 ; J1.25@1611.75,3381.75 2115,3885 ; J1.25@1611.75,3381.75 2115,3885 ; J1.25@1611.75,3381.75 2115,3885 ; v1@1965,2532.2 U8.7@2052.09,2532.2 ; v1@1965,2532.2 U8.7@2052.09,2532.2 ; v1@1965,2532.2 U8.7@2052.09,2532.2 ; v1@1965,2532.2 U8.7@2052.09,2532.2
  Bottom Layer w10: v1(1965,2535) 1965,3090 v1(2020,3145)
  Bottom Layer w12: v2(3545,3500) 3545,3405 3625,3325 3945,3325 ; v2(3945,3219.96) 3945,3325 ; v2(4485,3219.96) 4485,3325 3945,3325
BATT_GND: J22.1 Q1.D
BFL: Q2.G R10.2 U6.15 | length 371.7
  Top Layer w10: Q2.G@4880.63,3097.4 4952.4,3097.4 5055,3200 R10.2@5120.47,3200 5120.47,3230.47 5125,3235 U6.15@5125,3287.48
GND: C2.1 C3.- C4.1 C5.1 C7.1 C9.2 C10.2 C11.- C12.2 C13.1 C14.1 C15.1 D4.A D6.A D8.K D9.K D10.K D11.K D12.K D13.K D14.K D15.K D16.K D17.K D18.K D19.K D20.K D21.K D22.K D23.K J1.9 J1.10 J1.28 J1.29 J2.3 J3.3 J4.3 J5.3 J6.3 J7.3 J8.3 J9.3 J10.3 J11.3 J24.7 J25.2 J25.3 J26.3 J26.6 J26.9 J26.12 J26.15 J26.18 J26.21 J26.24 J26.27 J26.30 J26.33 J26.36 J26.39 J26.42 J27.2 J28.3 J28.6 J28.9 J28.12 J28.15 J28.18 J28.21 J28.24 pad.0 Q1.S Q2.S Q3.S Q4.S R1.1 R2.1 R6.1 R7.1 R10.1 R15.1 RP1.2 RP1.6 RP2.2 RP2.6 RP3.2 RP3.6 RP5.2 RP5.6 RP7.2 RP7.6 RP8.6 RP14.2 RP14.6 RP18.2 RP18.4 RP19.2 RP19.4 RP19.6 RP19.8 RP20.2 RP20.4 RP20.6 RP20.8 RP21.2 RP21.4 RP21.6 RP21.8 RP22.2 RP22.4 RP22.6 RP22.8 U2.10 U3.6 U3.PAD U4.8 U5.8 U6.8 U6.13 U7.6 U7.PAD U8.4 | length 8244.3
  Top Layer w10: 1155,3649.76 RP14.2@1188.5,3649.76 ; 1155,3712.76 RP14.6@1188.5,3712.76 ; 1155,3870 1155,3625 1180,3600 v3(1220,3600) ; 1155.22,2123.54 RP1.2@1188.72,2123.54 ; 1155.22,2186.54 RP1.6@1188.72,2186.54 ; 1155.22,2343.78 1155.22,2098.78 1180.22,2073.78 v3(1220.22,2073.78) ; 1155.22,2559.78 RP3.2@1188.72,2559.78 ; 1155.22,2622.77 RP3.6@1188.72,2622.77 ; 1155.22,2779.78 1155.22,2534.78 1180.22,2509.78 v3(1220.22,2509.78) ; 1155.22,3213.78 RP7.2@1188.72,3213.78 ; 1155.22,3276.77 RP7.6@1188.72,3276.77 ; 1155.22,3433.78 1155.22,3188.78 1180.22,3163.78 v3(1220.22,3163.78) ; 1155.46,3792.76 RP18.2@1188.96,3792.76 ; 1155.46,3824.25 RP18.4@1188.96,3824.25 ; 1155.68,2267.76 RP2.2@1189.18,2267.76 ; 1155.68,2330.75 RP2.6@1189.18,2330.75 ; 1155.68,2702.76 RP5.2@1189.18,2702.76 ; 1155.68,2765.75 RP5.6@1189.18,2765.75 ; 1155.68,3420.75 RP8.6@1189.18,3420.75 ; D8.K@3920.88,3790.88 D15.K@3920.88,3870.88 ; D9.K@4020.88,3790.88 D16.K@4020.88,3870.88 ; D10.K@4120.88,3790.88 D17.K@4120.88,3870.88 ; D18.K@4220.88,3870.88 D11.K@4220.88,3790.88 D19.K@4279.12,3790.88 D23.K@4279.12,3870.88 ; D12.K@4379.12,3790.88 D20.K@4379.12,3870.88 ; D13.K@4479.12,3790.88 D21.K@4479.12,3870.88 ; D14.K@4579.12,3790.88 D22.K@4579.12,3870.88 ; 5015,1900 R2.1@5061.61,1900 ; U6.13@5025,3287.48 v2(5025,3355) ; R1.1@5070.47,1800 5025,1800 5015,1810 5015,1950 5040,1975 R15.1@5122.91,1975
  Top Layer w12: U2.10@2100,2695 2070,2695 ; C15.1@2157.4,2420 C15.1@2162.4,2425 ; C15.1@2160,2420 2235,2420 v1(2260,2445) ; U8.4@2187.91,2583.39 2228.39,2583.39 2245,2600 v1(2300,2600) ; C5.1@2715,3147.6 C5.1@2712.4,3145 2712.4,3277.4 2715,3280 2715,3285 ; R7.1@2810,3169.53 2812.6,3172.13 v1@2812.6,3282.6 ; R6.1@3110,2499.53 3112.6,2502.13 v1@3112.6,2612.6 ; v1(3690,3470) U4.8@3742.48,3470 ; C9.2@4190,3417.4 v1(4190,3480) ; C10.2@4730,3417.4 v1(4730,3480) ; R10.1@5179.53,3200 5205,3200 C12.2@5240,3235 ; C12.2@5265,3240 v1(5327.6,3240) ; Q3.S@5614.37,3687.4 v4(5687.4,3687.4) ; Q4.S@5614.37,3862.4 v4(5687.4,3862.4) ; v1@2015,2640 v1@2022.5,2647.5 ; v1@2015,2640 2070,2695 ; v1@2015,2640 v1@2022.5,2647.5 ; v1@2015,2640 v1@2022.5,2647.5 ; v1@2022.5,2647.5 2070,2695 ; v1@2022.5,2647.5 2070,2695 ; v1@2022.5,2647.5 2070,2695 ; v1(4190,3480) U5.8@4285,3480 ; v1(4190,3480) U5.8@4285,3480 ; v1(4190,3480) U5.8@4285,3480 ; v1(4190,3480) U5.8@4285,3480 ; v1(4730,3480) U6.8@4825,3480 ; v1(4730,3480) U6.8@4825,3480 ; v1(4730,3480) U6.8@4825,3480 ; v1(4730,3480) U6.8@4825,3480
  Top Layer w15: RP19.8@3872.76,3928.5 4143.5,3928.5 4175,3960 4315,3960 4346.5,3928.5 RP20.2@4607.24,3928.5 ; D15.K@3920.88,3870.88 D22.K@4579.12,3870.88 ; 4250,3870.88 pad.0@4250,3960 ; 4250,3870.88 pad.0@4250,3960 ; 4250,3870.88 pad.0@4250,3960 ; 4250,3870.88 pad.0@4250,3960
  Top Layer w26: U7.PAD@3415,3380 C13.1@3415,3560 ; U7.6@3415,3470 C13.1@3415,3560 ; U7.6@3415,3470 C13.1@3415,3560 ; U7.6@3415,3470 C13.1@3415,3560 ; U3.6@3715,2800 C4.1@3715,2890 ; U3.6@3715,2800 C4.1@3715,2890 ; U3.6@3715,2800 C4.1@3715,2890 ; U3.6@3715,2800 C4.1@3715,2890
  Top Layer w30: C13.1@3427.4,3560 v1(3490,3560) ; C14.1@3427.4,3640 v1(3490,3640) ; C4.1@3727.4,2890 v1(3790,2890) ; v1(4880,2945) 4880,3010 ; C13.1@3415,3560 C14.1@3415,3640 ; C13.1@3415,3560 C14.1@3415,3640 ; C13.1@3415,3560 C14.1@3415,3640 ; C13.1@3415,3560 C14.1@3415,3640
  other v1: 4100,2440 4200,2440 4280,2440 4360,2440 4460,2440 4100,2540 4200,2540 3295,2615 3360,2615 2825,2620 3105,2640 2020,2650 2805,2865 2995,3285 3060,3285 2525,3290 2805,3310 2505,3535
  other v3: 5015,1845
GPIO1: J1.18 J26.1 RP1.3 | length 3837.1
  Top Layer w10: J1.18@1500,2128 1362.85,2128.02 1335.59,2155.28 ; RP1.3@1251.72,2155.28 1335.59,2155.28 ; RP1.3@1251.72,2155.28 1335.59,2155.28 ; RP1.3@1251.72,2155.28 1335.59,2155.28
  Bottom Layer w10: J1.18@1500,2128 1671,2128 1800,2257 1800,2663.22 1947,2810.22 1947,3097.46 1950,3100.46 1950,3590 2165,3805 3105,3805 J26.1@3400,4100
GPIO2: J1.17 J26.4 RP1.7 | length 3706.7
  Top Layer w12: J1.17@1500,2237 1346.12,2237.02 1327.37,2218.27 ; RP1.7@1251.72,2218.27 1327.37,2218.27 ; RP1.7@1251.72,2218.27 1327.37,2218.27 ; RP1.7@1251.72,2218.27 1327.37,2218.27 ; RP1.7@1251.72,2218.27 1327.37,2218.27
  Bottom Layer w10: J1.17@1500,2237 1680,2237 1775,2332 1775,2673.58 1925,2823.58 1925,3595 2155,3825 3025,3825 J26.4@3300,4100
GPIO3: J1.16 J26.7 RP2.3 | length 3290.5
  Top Layer w12: RP2.3@1251.72,2299.25 RP2.3@1252.17,2299.25 1351.79,2299.25 1398.55,2346.02 J1.16@1500,2346
  Bottom Layer w10: J1.16@1500,2346 1664,2346 1750,2432 1750,2683.93 1900,2833.93 1900,3600 2145,3845 2945,3845 J26.7@3200,4100
GPIO4: J1.15 J26.10 RP2.7 | length 3441.8
  Top Layer w12: J1.15@1500,2455 1450.97,2455 1357.98,2362.01 ; RP2.7@1251.72,2362.01 RP2.7@1252.17,2362.01 ; RP2.7@1251.72,2362.01 RP2.7@1252.17,2362.01 ; RP2.7@1251.72,2362.01 RP2.7@1252.17,2362.01 ; RP2.7@1252.17,2362.01 1357.98,2362.01 ; RP2.7@1252.17,2362.01 1357.98,2362.01 ; RP2.7@1252.17,2362.01 1357.98,2362.01 ; RP2.7@1252.17,2362.01 1357.98,2362.01
  Bottom Layer w10: J1.15@1500,2455 1673,2455 1725,2507 1725,2694.29 1875,2844.29 1875,3605 2135,3865 2865,3865 J26.10@3100,4100
GPIO5: J1.14 J26.13 RP3.3 | length 2894.2
  Top Layer w10: RP3.3@1251.72,2591.28 1335.59,2591.28 1362.85,2564.02 J1.14@1500,2564
  Bottom Layer w10: J1.14@1500,2564 1657,2564 1700,2607 1700,2704.64 1850,2854.64 1850,3607.85 2127.15,3885 2785,3885 J26.13@3000,4100
GPIO6: J1.13 J26.16 RP3.7 | length 2690.7
  Top Layer w12: RP3.7@1251.72,2654.27 1327.37,2654.27 1346.12,2673.02 J1.13@1500,2673
  Bottom Layer w10: J1.13@1500,2673 1641,2673 1675,2707 1675,2715 1825,2865 1825,3614.19 2115.81,3905 2705,3905 J26.16@2900,4100
GPIO7: J1.12 J26.19 RP5.3 | length 3328.8
  Top Layer w12: J1.12@1500,2782 1398.55,2782.02 1351.02,2734.49 ; RP5.3@1251.72,2734.49 RP5.3@1252.17,2734.49 ; RP5.3@1251.72,2734.49 RP5.3@1252.17,2734.49 ; RP5.3@1251.72,2734.49 RP5.3@1252.17,2734.49 ; RP5.3@1252.17,2734.49 1351.02,2734.49 ; RP5.3@1252.17,2734.49 1351.02,2734.49 ; RP5.3@1252.17,2734.49 1351.02,2734.49 ; RP5.3@1252.17,2734.49 1351.02,2734.49
  Bottom Layer w10: J26.19@2800,4100 2625,3925 2105,3925 1799.98,3619.98 1799.98,2914.02 1667.98,2782.02 ; J1.12@1500,2782 1667.98,2782.02 ; J1.12@1500,2782 1667.98,2782.02 ; J1.12@1500,2782 1667.98,2782.02 ; J1.12@1500,2782 1667.98,2782.02
GPIO8: J1.11 J26.22 RP5.7 | length 2714.4
  Top Layer w12: RP5.7@1251.72,2797.24 RP5.7@1252.17,2797.24 1357.21,2797.24 1450.97,2891 J1.11@1500,2891
  Bottom Layer w10: J26.22@2700,4100 2545,3945 2095,3945 1774.98,3624.98 1774.98,2989.02 1676.98,2891.02 ; J1.11@1500,2891 1676.98,2891.02 ; J1.11@1500,2891 1676.98,2891.02 ; J1.11@1500,2891 1676.98,2891.02
GPIO9: J1.8 J26.25 RP7.3 | length 2397.1
  Top Layer w10: RP7.3@1251.72,3245.28 1335.59,3245.28 1362.85,3218.02 J1.8@1500,3218
  Bottom Layer w10: J26.25@2600,4100 2465,3965 2085,3965 1749.98,3629.98 1749.98,3307.02 1660.98,3218.02 ; J1.8@1500,3218 1660.98,3218.02 ; J1.8@1500,3218 1660.98,3218.02 ; J1.8@1500,3218 1660.98,3218.02 ; J1.8@1500,3218 1660.98,3218.02
GPIO10: J1.7 J26.28 RP7.7 | length 2234.4
  Top Layer w12: RP7.7@1251.72,3308.27 1327.37,3308.27 1346.12,3327.02 J1.7@1500,3327
  Bottom Layer w10: J26.28@2500,4100 2385,3985 2075,3985 1724.98,3634.98 1724.98,3382.02 1669.98,3327.02 ; J1.7@1500,3327 1669.98,3327.02 ; J1.7@1500,3327 1669.98,3327.02 ; J1.7@1500,3327 1669.98,3327.02 ; J1.7@1500,3327 1669.98,3327.02
GPIO11: J1.6 J26.31 RP8.3 | length 2298
  Top Layer w12: J1.6@1500,3436 1398.55,3436.02 1352.02,3389.49 ; RP8.3@1251.72,3389.49 RP8.3@1252.17,3389.49 ; RP8.3@1251.72,3389.49 RP8.3@1252.17,3389.49 ; RP8.3@1251.72,3389.49 RP8.3@1252.17,3389.49 ; RP8.3@1251.72,3389.49 RP8.3@1252.17,3389.49 ; RP8.3@1252.17,3389.49 1352.02,3389.49 ; RP8.3@1252.17,3389.49 1352.02,3389.49 ; RP8.3@1252.17,3389.49 1352.02,3389.49 ; RP8.3@1252.17,3389.49 1352.02,3389.49
  Bottom Layer w10: J26.31@2400,4100 2305,4005 2065,4005 1699.98,3639.98 1699.98,3482.02 1653.98,3436.02 ; J1.6@1500,3436 1653.98,3436.02 ; J1.6@1500,3436 1653.98,3436.02 ; J1.6@1500,3436 1653.98,3436.02 ; J1.6@1500,3436 1653.98,3436.02
GPIO12: J1.5 J26.34 RP8.7 | length 1756.8
  Top Layer w12: RP8.7@1251.72,3452.24 RP8.7@1252.17,3452.24 1358.21,3452.24 1450.97,3545 J1.5@1500,3545
  Bottom Layer w10: J26.34@2300,4100 2225,4025 2055,4025 1670,3640 1670,3580 1635.02,3545.02 ; J1.5@1500,3545 1635.02,3545.02 ; J1.5@1500,3545 1635.02,3545.02 ; J1.5@1500,3545 1635.02,3545.02 ; J1.5@1500,3545 1635.02,3545.02
GPIO13: J1.4 J26.37 RP14.3 | length 1144.6
  Top Layer w10: RP14.3@1251.5,3681.26 1335.61,3681.26 1362.87,3654 J1.4@1500,3654
  Bottom Layer w10: J1.4@1500,3654 1654,3654 2045,4045 2145,4045 J26.37@2200,4100
GPIO14: J1.3 J26.40 RP14.7 | length 995.9
  Top Layer w12: RP14.7@1251.5,3744.25 1327.39,3744.25 1346.14,3763 J1.3@1500,3763
  Bottom Layer w12: J1.3@1500,3763 1733,3763 2035,4065 2065,4065 J26.40@2100,4100
I2C_SCL: J1.1 J24.3 J25.5 Q3.D R11.1 RP18.7 | length 5158.2
  Top Layer w12: RP18.7@1251.73,3887.24 RP18.7@1251.95,3887.24 1357.24,3887.24 1450.98,3980.98 J1.1@1500.02,3980.98 1800.98,3980.98 1845,4025 v3(3725,4025) ; J24.3@5150,3725 5200,3675 5425,3675 5450,3650 Q3.D@5535.63,3650 5535.63,3614.37 5570.47,3579.53 R11.1@5570.47,3525
  Power Routing w12: J24.3@5150,3725 5150,3799.21 5260.24,3909.45 J25.5@5260.24,4007.87
  Bottom Layer w12: v3(3725,4025) 3860,3890 4960,3890 5015,3835 5185.79,3835 5260.24,3909.45 J25.5@5260.24,4007.87
I2C_SCL_A: J1.21 Q3.G RP18.1 | length 4723
  Top Layer w12: RP18.1@1255,3792.24 1347.1,3792.24 1372.35,3817.5 J1.21@1612,3817.5 1737.5,3817.5 1885,3965 3575,3965 v3(3620,3920) ; Q3.G@5614.37,3612.6 v4(5687.4,3612.6)
  Bottom Layer w12: v3(3620,3920) 3710,3830 4935.15,3830 4990.15,3775 5525,3775 v4(5687.4,3612.6)
I2C_SDA: J1.20 J24.5 J25.6 Q4.D R12.1 RP18.5 | length 5707.1
  Top Layer w12: v3(3690,3990) 3675,4005 1855,4005 1776.5,3926.5 J1.20@1612,3926.5 1424.78,3926.5 1354.27,3855.98 ; J24.5@5250,3725 5350,3825 Q4.D@5535.63,3825 5535.63,3860.63 5570.47,3895.47 R12.1@5570.47,3950 ; RP18.5@1251.5,3855.98 RP18.5@1251.95,3855.98 ; RP18.5@1251.5,3855.98 RP18.5@1251.95,3855.98 ; RP18.5@1251.5,3855.98 RP18.5@1251.95,3855.98 ; RP18.5@1251.95,3855.98 1354.27,3855.98 ; RP18.5@1251.95,3855.98 1354.27,3855.98 ; RP18.5@1251.95,3855.98 1354.27,3855.98 ; RP18.5@1251.95,3855.98 1354.27,3855.98
  Power Routing w12: J24.5@5250,3725 5350,3825 5350,4058.27 J25.6@5300.39,4107.87
  Bottom Layer w12: v3(3690,3990) 3810,3870 4951.72,3870 5006.72,3815 5240,3815 5350,3925 5350,4058.27 J25.6@5300.39,4107.87
I2C_SDA_A: J1.2 Q4.G RP18.3 | length 4955.9
  Top Layer w12: v3(3655,3955) 3625,3985 1870,3985 1757,3872 J1.2@1500,3872 1398.57,3872 1351.06,3824.49 ; Q4.G@5614.37,3787.6 v4(5687.4,3787.6) ; RP18.3@1251.5,3824.49 RP18.3@1251.95,3824.49 ; RP18.3@1251.5,3824.49 RP18.3@1251.95,3824.49 ; RP18.3@1251.5,3824.49 RP18.3@1251.95,3824.49 ; RP18.3@1251.5,3824.49 RP18.3@1251.95,3824.49 ; RP18.3@1251.95,3824.49 1351.06,3824.49 ; RP18.3@1251.95,3824.49 1351.06,3824.49 ; RP18.3@1251.95,3824.49 1351.06,3824.49 ; RP18.3@1251.95,3824.49 1351.06,3824.49
  Bottom Layer w12: v3(3655,3955) 3760,3850 4943.43,3850 4998.43,3795 5580,3795 5587.4,3787.6 v4(5687.4,3787.6)
NetC1_1: C1.1 U3.1 | length 85.5
  Top Layer w25: C1.1@3615,2494.53 U3.1@3615,2580
NetC1_2: C1.2 D4.K L1.1 U3.8 | length 368.7
  Top Layer w30: D4.K@3488.74,2530 3528.74,2490 C1.2@3550,2490
  Top Layer w60: D4.K@3488.74,2530 3488.74,2628.74 3515.04,2655.04 L1.1@3515.04,2810
NetC8_1: C8.1 U7.1 | length 85.5
  Top Layer w25: C8.1@3315,3164.53 U7.1@3315,3250
NetC8_2: C8.2 D6.K L2.1 U7.8 | length 368.7
  Top Layer w30: D6.K@3188.74,3200 3228.74,3160 C8.2@3250,3160
  Top Layer w60: D6.K@3188.74,3200 3188.74,3298.74 3215.04,3325.04 L2.1@3215.04,3480
NetCB2_1: CB2.1 D5.K D7.A J23.2 | length 1090.3
  Top Layer w12: 5642.66,2917.34 5681.34,2956.02 D7.A@5681.34,3060
  Top Layer w30: CB2.1@5237.68,2895 5237.68,3050.91 5314.09,3050.91 5400,2965 5400,2890 5500,2790 5650,2790 5675,2815 5675,2885 5642.66,2917.34 J23.2@5600,2960
NetD1_K: D1.K R1.2 | length 1078.4
  Top Layer w12: R1.2@5129.53,1800 R1.2@5138.39,1800 5097.81,1759.43 5015.57,1759.43 4950,1825 4950,1950 5050,2050 5408.66,2050 D1.K@5558.66,2200
NetD2_K: D2.K R2.2 | length 461.7
  Top Layer w12: R2.2@5138.39,1900 5458.66,1900 D2.K@5558.66,2000
NetD3_K: D3.K R14.2 | length 275.9
  Top Layer w12: R14.2@5307.91,1860.83 5497.83,1860.83 D3.K@5558.66,1800
NetD5_A: D5.A J23.1 Q2.D R9.1 | length 822
  Top Layer w30: Q2.D@4959.37,3060 D5.A@5051.42,3060 5131.42,3140 5310,3140 5398.96,3051.04 5500,2950 5500,2895 5535,2860 J23.1@5600,2860
NetD7_K: D7.K R9.2 | length 60.5
  Top Layer w12: R9.2@5540,3060 D7.K@5598.66,3060 D7.K@5600.47,3060
NetD8_A: D8.A RP16.3 | length 180.1
  Top Layer w8: RP16.3@3775.75,3626.5 3775.75,3650.75 3795,3670 3795,3690 3830,3725 3855,3725 D8.A@3879.12,3749.12
NetD9_A: D9.A RP9.3 | length 138
  Top Layer w8: RP9.3@3915.75,3626.5 3915.75,3665.75 3920,3670 3920,3685 D9.A@3975,3740
NetD10_A: D10.A RP15.3 | length 132.3
  Top Layer w8: RP15.3@4055.75,3626.5 4055.75,3660.75 4065,3670 4065,3700 4079.12,3714.12 D10.A@4079.12,3749.12
NetD11_A: D11.A RP10.3 | length 128.7
  Top Layer w8: D11.A@4179.12,3749.12 4193.73,3734.51 RP10.3@4193.74,3626.5
NetD12_A: D12.A RP12.3 | length 143.3
  Top Layer w8: D12.A@4420.88,3749.12 4463.74,3706.26 4463.74,3671.26 4470.75,3664.25 RP12.3@4470.75,3626.5
NetD13_A: D13.A RP17.3 | length 174.5
  Top Layer w8: D13.A@4520.88,3749.12 4540,3730 4565,3730 4610.75,3684.25 RP17.3@4610.75,3626.5
NetD14_A: D14.A RP13.3 | length 211.6
  Top Layer w8: D14.A@4620.88,3749.12 4680.88,3749.12 4735,3695 4735,3670 4750.75,3654.25 RP13.3@4750.75,3626.5
NetD15_A: D15.A RP16.7 | length 283.2
  Top Layer w8: RP16.7@3712.76,3626.5 3712.76,3682.76 3800,3770 3820,3770 D15.A@3879.12,3829.12
NetD16_A: D16.A RP9.7 | length 255
  Top Layer w8: RP9.7@3852.76,3626.5 3852.76,3657.76 3860,3665 3860,3690 3960,3790 3960,3810 D16.A@3979.12,3829.12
